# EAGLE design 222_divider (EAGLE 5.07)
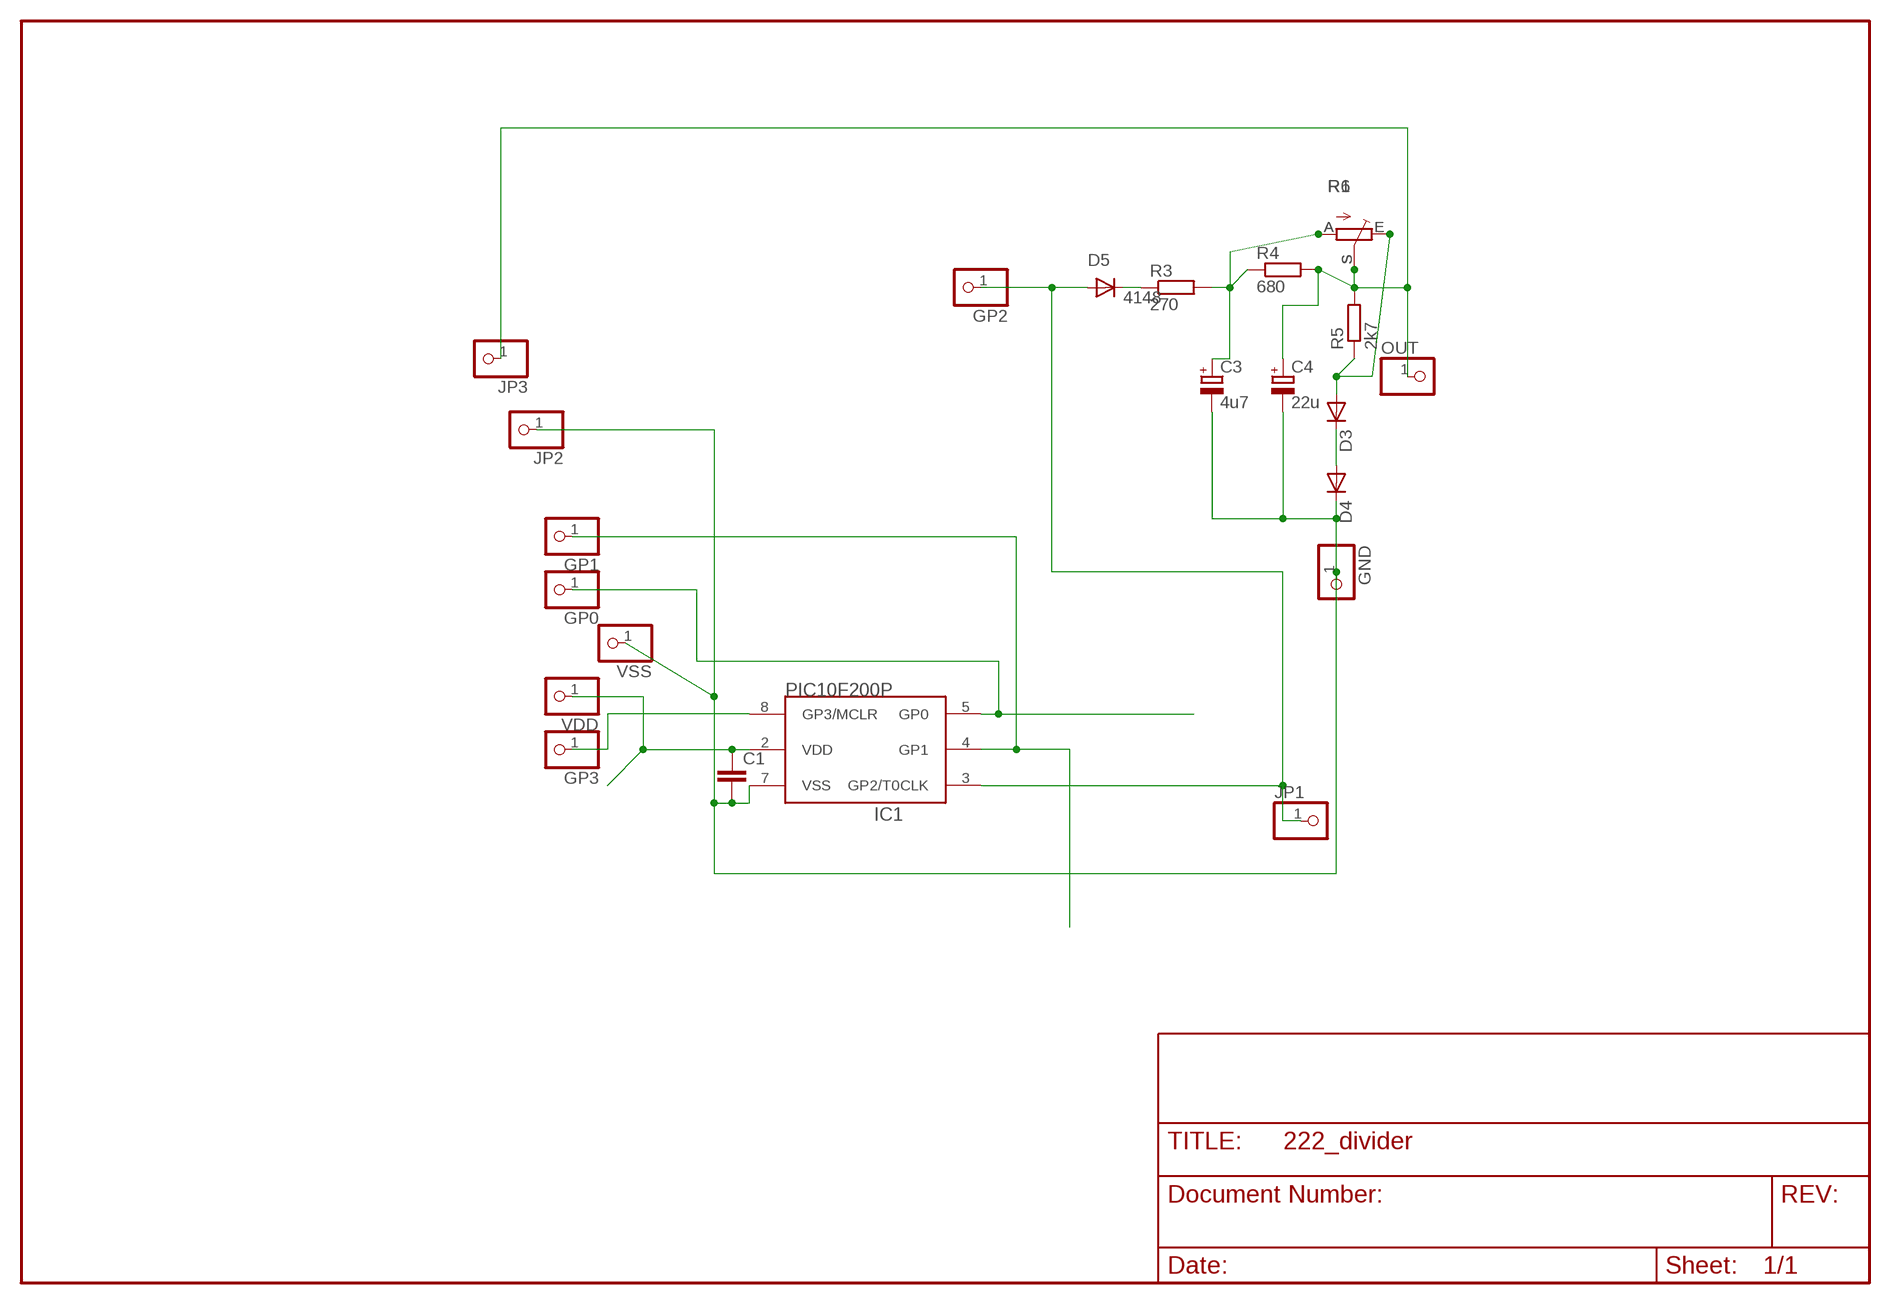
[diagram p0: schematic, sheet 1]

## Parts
C1  C-EUC0805  [C0805]
C3  4u7  CPOL-EUSMCA  [SMC_A]
C4  22u  CPOL-EUSMCA  [SMC_A]
D3  DIODE-SOD80C  [SOD80C]
D4  DIODE-SOD80C  [SOD80C]
D5  4148  DIODE-SOD80C  [SOD80C]
GND  PINHD-1X11X0.4  [1X01]
GP0  PINHD-1X1  [1X01]
GP1  PINHD-1X1  [1X01]
GP2  PINHD-1X11X0.4  [1X01]
GP3  PINHD-1X1  [1X01]
IC1  PIC10F200P  [DIL8]
JP1  PINHD-1X1  [1X01]
JP2  PINHD-1X1  [1X01]
JP3  PINHD-1X1  [1X01]
OUT  PINHD-1X11X0.4  [1X01]
R1  TRIM_EU-S64W  [S64W]
R3  270  R-EU_R0805  [R0805]
R4  680  R-EU_R0805  [R0805]
R5  2k7  R-EU_R0805  [R0805]
R6  TRIM_EU-CA6V  [CA6V]
VDD  PINHD-1X1  [1X01]
VSS  PINHD-1X1  [1X01]

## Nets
DR1: D5.C R3.1
DR2: D3.A R1.E R5.1 R6.E
GND: C1.2 C3.- C4.- D4.C GND.1 IC1.7(VSS) JP2.1 VSS.1
GP0: GP0.1 IC1.5(GP0)
GP1: GP1.1 IC1.4(GP1)
GP2: D5.A GP2.1 IC1.3(GP2/T0CLK) JP1.1
GP3: GP3.1 IC1.8(GP3/MCLR)
N$2: D3.C D4.A
OUT: C4.+ JP3.1 OUT.1 R1.S R4.2 R5.2 R6.S
RRC: C3.+ R1.A R3.2 R4.1 R6.A
VDD: C1.1 IC1.2(VDD) VDD.1

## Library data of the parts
C1 = rcl:C-EU: CAPACITOR, European symbol
C3 C4 = rcl:CPOL-EU: POLARIZED CAPACITOR, European symbol
D3-D5 = diode:DIODE-: DIODE
GND GP2 OUT = pinhead:PINHD-1X1: PIN HEADER
GP0 GP1 GP3 JP1-JP3 VDD VSS = pinhead(2):PINHD-1X1: PIN HEADER
IC1 = microchip-3:PIC10F20*: uPC nW 0,25/0,5k Program Flash memory
R1 R6 = pot:TRIM_EU-: POTENTIOMETER
R3-R5 = rcl:R-EU_: RESISTOR, European symbol

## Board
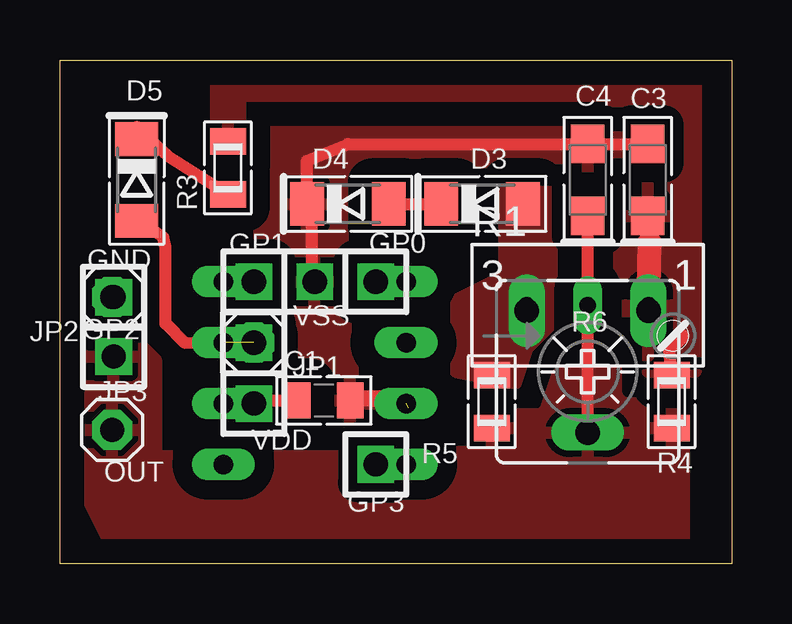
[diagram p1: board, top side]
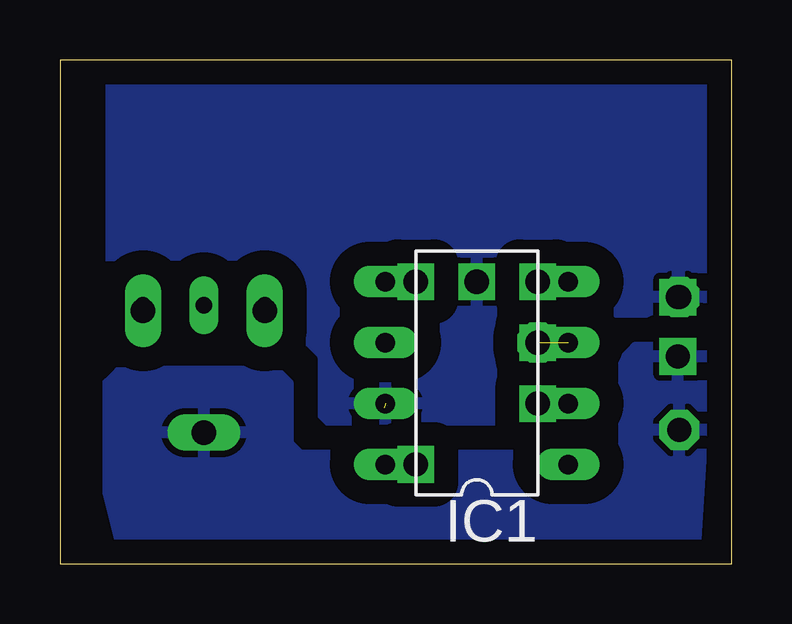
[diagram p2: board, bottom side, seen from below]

Size 28 x 21 mm. Coordinates in mm from the lower left corner, seen from the top.
Outline: 0,0 0,21 28,21 28,0 0,0
Copper layers (1*16): Top 0.035mm / dielectric 1.5mm / Bottom 0.035mm
Design rules "default": minimum track width 10mil, minimum drill 24mil, track to track 8mil, track to pad 8mil, pad to pad 8mil, via to via 8mil, smd to smd 8mil, copper to edge 40mil, drill to drill 8mil, minimum pad ring 10mil, minimum via ring 8mil, stop-mask expansion 4mil, vias tented up to drill 0mil, thermal gap 10mil

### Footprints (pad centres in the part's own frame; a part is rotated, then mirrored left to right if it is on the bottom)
C0805 = smd 1.1 x 1.5: 1 -1.1,0; 2 1.1,0
SMC_A = smd 1.6 x 1.4: + -1.5,0; - 1.5,0
SOD80C = smd 1.4 x 1.8: A 1.7,0; C -1.7,0
1X01 = drill 1 pad 1.676 octagon: 1 0,0
1X01' = drill 1.016 square: 1 0,0
DIL8 = drill 0.813 long: 1 -3.81,-3.81; 2 -1.27,-3.81; 3 1.27,-3.81; 4 3.81,-3.81; 5 3.81,3.81; 6 1.27,3.81; 7 -1.27,3.81; 8 -3.81,3.81
S64W = drill 0.7 long: A 2.54,1.27; E -2.54,1.27; S 0,1.27
R0805 = smd 1.1 x 1.5: 1 -1.1,0; 2 1.1,0
CA6V = drill 1.016 long: A -2.54,-2.54; E 2.54,-2.54; S 0,2.54

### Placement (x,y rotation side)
C1  11,6.8 0 top
C3  24.5,16 90 top
C4  22,16 90 top
D3  17.6,15 0 top
D4  12,15 0 top
D5  3.2,16 270 top
GND  2.17,11.11 0 top
GP0  [1X01']  13.16,11.76 0 top
GP1  [1X01']  8.08,11.76 0 top
GP2  8.08,9.21 0 top
GP3  [1X01']  13.16,4.13 0 top
IC1  10.62,7.95 90 bottom
JP1  [1X01']  8.08,9.21 90 top
JP2  [1X01']  2.24,11.11 90 top
JP3  [1X01']  2.24,8.64 90 top
OUT  2.17,5.57 0 top
R1  22,9.5 0 top
R3  7,16.5 90 top
R4  25.5,6.75 270 top
R5  18,6.75 270 top
R6  22,8 180 top
VDD  [1X01']  8.08,6.67 0 top
VSS  [1X01']  10.62,11.76 0 top

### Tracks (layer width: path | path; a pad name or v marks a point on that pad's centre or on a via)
DR1
  Top 0.5: D5.C 3.2,18.2 4.5,17 R3.1
DR2
  pour Top (isolate 0.8, rank 3, no thermals): 20.5,10 20.5,15.5 18.5,15.5 18.5,12 16.5,11 16.5,8 19,7.5 19.5,9
GND  (1 unrouted)
  Top 0.5: 10.5,12.59 10.5,14 D4.C 10.3,16.8 12,17.5 C4.- C3.- | 10.5,11.93 VSS.1 | 12.5,7 14.5,7 14.5,6.5 | C1.2 14.43,6.8 IC1.7
  pour Bottom (isolate 1, rank 3): 1.04,20.32 25.86,20.32 25.86,2.54 1.04,2.04
  pour Top (isolate 1, rank 3): 1.04,18.32 25.86,18.32 26.36,15.54 25.86,15.14 23.5,15 15,16 13.5,15.5 13.5,4 8.5,4 8.46,12.04 3.5,12 2.46,13.04 1.04,13.04
GP0
  Top 0.5: IC1.5 GP0.1
GP1
  Top 0.5: IC1.4 GP1.1
GP2  (1 unrouted)
  Top 0.5: GP2.1 5.2,9.2 4.4,10 4.4,13.2 4.31,13.61 D5.A
GP3
  Top 0.5: IC1.8 14.5,4.13 14.5,4 13.16,4 GP3.1
N$2
  Top 0.5: D4.A D3.C
OUT
  Top 0.5: 22.05,5.45 R6.S R1.S C4.+
  pour Top (isolate 0.813, rank 4): 20,8 24.5,8 26,5.5 26,1 2,1 1,3 1,9 3.5,9 4,8.5 4,4.5 15.5,4.5 18.5,5 18.5,6.5
  pour Bottom (isolate 1, rank 2): 19,8 25.5,8 26,7.5 26,3 25.5,1 1.5,1 1,9 4,9 4.5,8.5 4.5,4.5 18,4.5 18.5,5 18.5,7.5
RRC
  Top 0.5: R4.1 25.41,8.91 26,9.5
  Top 1: R6.A 24.59,13.38
  pour Top (isolate 0.8, rank 2): 6.5,20.5 25.5,20.5 26.5,20 26.5,8 24.5,8 24.5,9 23,9 23,19.5 8.5,19.5 7.5,19.5 7.5,17.5 6.5,17.5
VDD
  Top 0.5: C1.1 8.08,6.8 VDD.1 8,6.67 8,6.5 6.81,6.5 IC1.2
